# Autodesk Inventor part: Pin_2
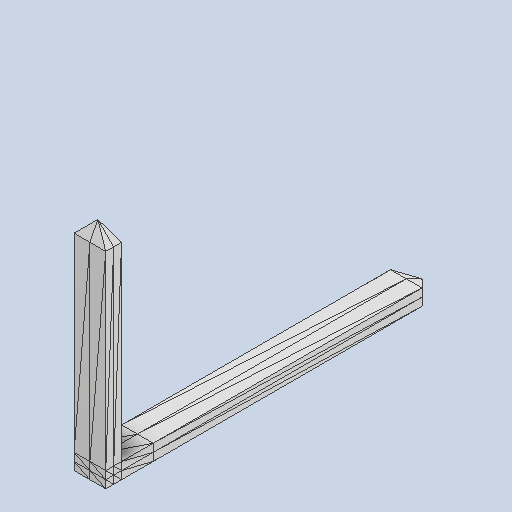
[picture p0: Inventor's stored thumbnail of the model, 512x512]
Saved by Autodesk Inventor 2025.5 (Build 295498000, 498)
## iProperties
Created: 2026-10
Part Number: Pin_2
Material: Genérico
Document SubType Name: Modeling
Designer: Luis M
Density: 1 g/cm^3
Appearance: Valor por defecto
Author: Luis M
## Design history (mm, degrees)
feature "Base1"
node "Sólido1"
